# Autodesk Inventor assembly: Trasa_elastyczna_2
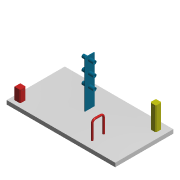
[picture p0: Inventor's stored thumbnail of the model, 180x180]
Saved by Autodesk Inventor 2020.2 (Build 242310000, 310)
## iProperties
Created: 2014-08
Part Number: Trasa_elastyczna_2
Document SubType Name: Assembly
Designer: F.Stasiak
Catalog Web Link: www.expertbooks.pl
Manager: www.cadconsulting.pl
Company: Fabian Stasiak CAD Consulting
Author: F.Stasiak
Subject: Zbiór ćwiczeń. Autodesk Inventor 2020. Kurs Professional
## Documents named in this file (2)
- C:\2020_Kurs_Professional\R1 Rury\Trasa_elastyczna_2.iam
- C:\2020_Kurs_Professional\R1 Rury\Konstrukcja_elastyczna_2.ipt
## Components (1 placed, 1 different names)
1. Konstrukcja_elastyczna_2:1
